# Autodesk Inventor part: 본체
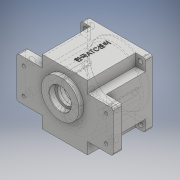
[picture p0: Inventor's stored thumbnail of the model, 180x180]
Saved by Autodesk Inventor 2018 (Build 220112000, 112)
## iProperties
Created: 2020-07
Part Number: 본체
Material: 일반
Document SubType Name: Modeling
Designer: Admin
Density: 1 g/cm^3
Appearance: 기본값
Author: Admin
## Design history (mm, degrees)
sketch "스케치5"
  geometry: L1 (47, 47)-(-47, 47); L2 (-47, 47)-(-47, -47); L3 (-47, -47)-(47, -47); L4 (47, -47)-(47, 47); L5 (47, 47)-(-47, -47); L6 (-47, 47)-(47, -47); 1 further point
  constraints: 12 end point, 2 midpoint, 2 parallel, 1 horizontal, 1 perpendicular
  dimensions: "d16" = 94 distance of L1.start L1.end; "d17" = 94 distance of L1.end L2.end
extrude "돌출5" new body sketch "스케치5" distance "d18" = 10; taper "d19" = 0 deg
sketch "스케치6"
  geometry: L1 (-33, 47)-(33, 47); L2 (33, 47)-(33, -47); L3 (33, -47)-(-33, -47); L4 (-33, -47)-(-33, 47); L5 (-33, 47)-(33, -47); L6 (33, 47)-(-33, -47); 1 further point
  constraints: 12 end point, 2 midpoint, 2 parallel, 1 horizontal, 1 perpendicular
  dimensions: "d20" = 66 distance of L1.start L1.end; "d21" = 94 distance of L1.end L2.end
extrude "돌출6" join sketch "스케치6" distance "d22" = 57; taper "d23" = 0 deg
sketch "스케치7"
  geometry: L1 (70, 30)-(70, -30); L2 (-70, -30)-(-70, 30); L3 (-70, 30)-(70, -30); L4 (70, 30)-(-70, -30); L5 (-33, 47)-(33, 47); L6 (33, -47)-(-33, -47); L7 (-33, 47)-(33, -47); L8 (33, 47)-(-33, -47); L9 (-70, 30)-(-33, 30); L10 (33, 30)-(70, 30); L11 (33, 47)-(33, 30); L12 (33, -30)-(33, -47); L13 (70, -30)-(33, -30); L14 (-33, -30)-(-70, -30); L15 (-33, -47)-(-33, -30); L16 (-33, 30)-(-33, 47); 1 further point
  constraints: 32 end point, 10 parallel, 4 midpoint, 4 perpendicular, 3 horizontal
  dimensions: "d24" = 140 distance of L2.end L1.start; "d25" = 60 distance of L1.start L1.end; "d26" = 66 distance of L5.start L5.end; "d27" = 94 distance of L5.end L6.start
extrude "돌출7" join sketch "스케치7" distance "d28" = 13; taper "d29" = 0 deg
sketch "스케치8"
  geometry: L1 (-103, 0)-(-66, 0) reference; L2 (-66, 0)-(-66, -13) reference; L3 (-103, -13)-(-66, -13) reference; L4 (-103, 0)-(-103, -13) reference; L5 (14, 67)-(-80, 67) reference; L6 (14, 67)-(14, 57) reference; L7 (0, 57)-(14, 57) reference; L8 (0, 57)-(0, -13) reference; L9 (-66, -13)-(0, -13) reference; L10 (-66, 57)-(-66, -13) reference; L11 (-80, 57)-(-66, 57) reference; L12 (-80, 67)-(-80, 57) reference; L13 (0, 0)-(37, 0) reference; L14 (37, 0)-(37, -13) reference; L15 (0, -13)-(37, -13) reference; L16 (0, 0)-(0, -13) reference; L17 (-80, 67)-(-80, 57) reference; L18 (-80, 57)-(-80, 0); L19 (-103, 0)-(-66, 0) reference; L20 (-80, 0)-(-66, 0); L21 (-66, 0)-(-66, 57); L22 (-80, 57)-(-66, 57) reference; L23 (-66, 57)-(-80, 57); L24 (14, 57)-(14, 0); L25 (0, 0)-(37, 0) reference; L26 (14, 0)-(0, 0); L27 (0, 57)-(0, -13) reference; L28 (0, 57)-(13.166, 57); L29 (0, 57)-(14, 57) reference; L30 (0, 57)-(0, 0); 1 further point
  constraints: 16 end point, 4 collinear, 4 point on line, 2 perpendicular
extrude "돌출8" join sketch "스케치8" distance "d30" = 60; taper "d31" = 0 deg
sketch "스케치9"
  geometry: L1 (-70, 30)-(-70, -30) reference; L2 (-70, -30)-(-33, -30) reference; L3 (-33, -30)-(-33, -47) reference; L4 (-33, -47)-(33, -47) reference; L5 (33, -47)-(33, -30) reference; L6 (33, -30)-(70, -30) reference; L7 (70, -30)-(70, 30) reference; L8 (70, 30)-(33, 30) reference; L9 (33, 30)-(33, 47) reference; L10 (33, 47)-(-33, 47) reference; L11 (-33, 47)-(-33, 30) reference; L12 (-33, 30)-(-70, 30) reference; L13 (-104.394, 11)-(123.857, 11); L14 (0, -65.8)-(0, 65.8) reference; C1 r 27.5 at (0, 11); 1 further point
  constraints: 2 end point, 2 point on line, 1 centre point, 1 horizontal
  dimensions: "d32" = 11 distance from line of L13 point (0, 0); "d33" = 55 diameter of C1
extrude "돌출9" join sketch "스케치9" distance "d34" = 7; taper "d35" = 0 deg
sketch "스케치10"
  geometry: C1 r 27.5 at (0, 0) reference; C2 r 16 at (0, 0); 1 further point
  constraints: 1 centre point, 1 coincident
  dimensions: "d36" = 32 diameter of C2
extrude "돌출10" cut sketch "스케치10" distance "d37" = 8.3; taper "d38" = 0 deg
sketch "스케치11"
  geometry: C1 r 16 at (0, 0) reference; C2 r 12.5 at (0, 0); 1 further point
  constraints: 1 centre point, 1 coincident
  dimensions: "d39" = 25 diameter of C2
extrude "돌출11" cut sketch "스케치11" distance "d40" = 4.7; taper "d41" = 0 deg
sketch "스케치12"
  geometry: C1 r 12.5 at (0, 0) reference; C2 r 17.5 at (0, 0); 1 further point
  constraints: 1 centre point, 1 coincident
  dimensions: "d42" = 35 diameter of C2
extrude "돌출12" cut sketch "스케치12" distance "d43" = 10; taper "d44" = 0 deg
sketch "스케치13"
  geometry: C1 r 43 at (0, 0); 1 further point
  constraints: 1 centre point, 1 coincident
  dimensions: "d45" = 86 diameter of C1
extrude "돌출13" cut sketch "스케치13" distance "d46" = 9; taper "d47" = 0 deg
sketch "스케치14"
  geometry: L1 (-98, 0)-(98, 0) reference; L2 (0, 65.8)-(0, -65.8) reference; L3 (35.778, -3.994)-(39.8, -3.994); L4 (35.778, 3.994)-(39.8, 3.994); L5 (-35.778, -3.994)-(-39.8, -3.994); L6 (-35.778, 3.994)-(-39.8, 3.994); A1 r 36 centre (0, 0) between (36, 0) and (-36, 0); A2 r 4 centre (36, 0) between (36.222, 3.994) and (36.222, -3.994); A3 r 4 centre (-36, 0) between (-36.222, -3.994) and (-36.222, 3.994); A4 r 40 centre (0, 0) between (39.8, 3.994) and (-39.8, 3.994); A5 r 40 centre (0, 0) between (-39.8, -3.994) and (39.8, -3.994); 1 further point
  constraints: 18 point on circle, 8 end point, 8 point on line, 5 centre point, 2 coincident, 1 horizontal, 1 parallel
  dimensions: "d49" = 72 diameter of A1; "d50" = 8 diameter of A3; "d51" = 8 diameter of A2; "d52" = 40 radius of A5; "d53" = 40 radius of A4
extrude "돌출14" cut sketch "스케치14" distance "d54" = 55; taper "d55" = 0 deg
sketch "스케치15"
  geometry: L1 (-78.7, -5)-(-78.7, 27) reference; L2 (-87, -5)-(-87, 27) reference; L3 (-87, 27)-(-78.7, 27) reference; L4 (-87, -5)-(-78.7, -5) reference; L5 (-86.2, 27)-(-87, 27.462); L6 (-87, 27.462)-(-87, 27); L7 (-87, 38.5)-(-87, -16.5) reference; L8 (-87, 27)-(-86.2, 27); L9 (-107.231, 11)-(-35.59, 11); 1 further point
  constraints: 8 end point, 1 collinear, 1 horizontal, 1 perpendicular, 1 point on line
  dimensions: "d56" = 30 deg angle of L3 L5; "d57" = 0.8 distance from line of L7 L5.start; "d58" = 16 distance between parallel lines of L9 L3
revolve "회전1" sketch "스케치15" stored, may be unused: angle "d59" = 90 deg
sketch "스케치16"
  geometry: L1 (83.382, 20)-(-123.857, 20); L2 (-165.305, 0)-(124.83, 0) reference; L3 (0, 65.8)-(0, -65.8) reference; C1 r 11 at (0, 20); 1 further point
  constraints: 2 end point, 2 point on line, 1 centre point, 1 horizontal
  dimensions: "d60" = 20 distance from line of point (0, 0) L1; "d61" = 22 diameter of C1
extrude "돌출15" cut sketch "스케치16" distance "d62" = 7; taper "d63" = 0 deg
sketch "스케치17"
  geometry: C1 r 11 at (0, 0) reference; C2 r 9.5 at (0, 0); 1 further point
  constraints: 1 centre point, 1 coincident
  dimensions: "d64" = 19 diameter of C2
extrude "돌출16" cut sketch "스케치17" distance "d65" = 3; taper "d66" = 0 deg
sketch "스케치18"
  geometry: C1 r 17.5 at (0, -11) reference; C2 r 11 at (0, 20) reference; C3 r 40 at (0, 0); A1 r 21 centre (0, -11) between (-8.978, 7.984) and (8.978, 7.984); A2 r 15 centre (0, 20) between (8.978, 7.984) and (-8.978, 7.984); 1 further point
  constraints: 4 point on circle, 3 centre point, 3 coincident
  dimensions: "d67" = 42 diameter of A1; "d68" = 30 diameter of A2; "d69" = 80 diameter of C3
extrude "돌출17" cut sketch "스케치18" distance "d70" = 7; taper "d71" = 0 deg
sketch "스케치19"
  geometry: A1 r 4 centre (36, 0) between (36.222, 3.994) and (36.222, -3.994) reference; A2 r 4 centre (-36, 0) between (-36.222, -3.994) and (-36.222, 3.994) reference; 3 further points
  constraints: 2 coincident
hole "구멍1" sketch "스케치19" at (36, 0), (-36, 0) diameter "d72" = 3.242; stored, may be unused: countersink angle "d76" = 90 deg, drill point angle "d78" = 118 deg; dims "d73" = 7, "d74" = 4, "d75" = 2, "d77" = 9
sketch "스케치20"
  geometry: L1 (-70, 30)-(-70, -30) reference; L2 (-70, -30)-(-33, -30) reference; L3 (-33, -30)-(-33, -47) reference; L4 (-33, -47)-(33, -47) reference; L5 (33, -47)-(33, -30) reference; L6 (33, -30)-(70, -30) reference; L7 (70, -30)-(70, 30) reference; L8 (70, 30)-(33, 30) reference; L9 (33, 30)-(33, 47) reference; L10 (33, 47)-(-33, 47) reference; L11 (-33, 47)-(-33, 30) reference; L12 (-33, 30)-(-70, 30) reference; L13 (-60, 19)-(60, 19); L14 (60, 19)-(60, -19); L15 (60, -19)-(-60, -19); L16 (-60, -19)-(-60, 19); L17 (-60, 19)-(60, -19); L18 (60, 19)-(-60, -19); C1 r 27.5 at (0, 11) reference; C2 r 2.25 at (-60, 19); C3 r 2.25 at (-60, -19); C4 r 2.25 at (60, -19); C5 r 2.25 at (60, 19); 1 further point
  constraints: 12 end point, 4 centre point, 4 coincident, 2 midpoint, 2 parallel, 1 horizontal, 1 perpendicular
  dimensions: "d79" = 38 distance of L13.end L14.end; "d80" = 120 distance of L13.start L13.end; "d81" = 4.5 diameter of C2; "d82" = 4.5 diameter of C3; "d83" = 4.5 diameter of C4; "d84" = 4.5 diameter of C5
extrude "돌출18" cut sketch "스케치20" distance "d85" = 8; taper "d86" = 0 deg
sketch "스케치21"
  geometry: L1 (-130, 11)-(-130, -49) reference; L2 (-130, -49)-(-93, -49) reference; L3 (-93, -49)-(-93, -66) reference; L4 (-93, -66)-(-27, -66) reference; L5 (-27, -66)-(-27, -49) reference; L6 (-27, -49)-(10, -49) reference; L7 (10, -49)-(10, 11) reference; L8 (10, 11)-(-27, 11) reference; L9 (-27, 11)-(-27, 28) reference; L10 (-27, 28)-(-93, 28) reference; L11 (-93, 28)-(-93, 11) reference; L12 (-93, 11)-(-130, 11) reference; C1 r 2.25 at (0, -38) reference; C2 r 2.25 at (-120, 0) reference; C3 r 2.25 at (-120, -38) reference; C4 r 2.25 at (0, 0) reference; C5 r 27.5 at (-60, -8) reference; C6 r 5 at (-120, 0); C7 r 5 at (-120, -38); C8 r 5 at (0, -38); C9 r 5 at (0, 0); 1 further point
  constraints: 4 centre point, 4 coincident
  dimensions: "d87" = 10 diameter of C9; "d88" = 10 diameter of C8; "d89" = 10 diameter of C7; "d90" = 10 diameter of C6
extrude "돌출19" cut sketch "스케치21" distance "d91" = 5; taper "d92" = 0 deg
sketch "스케치22"
  geometry: L1 (-40, 40)-(40, 40); L2 (40, 40)-(40, -40); L3 (40, -40)-(-40, -40); L4 (-40, -40)-(-40, 40); L5 (-40, 40)-(40, -40); L6 (40, 40)-(-40, -40); C1 r 3.5 at (-40, 40); C2 r 3.5 at (40, 40); C3 r 3.5 at (40, -40); C4 r 3.5 at (-40, -40); 1 further point
  constraints: 12 end point, 4 centre point, 4 coincident, 2 midpoint, 2 parallel, 1 horizontal, 1 perpendicular
  dimensions: "d93" = 80 distance of L1.start L1.end; "d94" = 80 distance of L1.end L2.end; "d95" = 7 diameter of C1; "d96" = 7 diameter of C2; "d97" = 7 diameter of C3; "d98" = 7 diameter of C4
extrude "돌출20" cut sketch "스케치22" distance "d99" = 10; taper "d100" = 0 deg
sketch "스케치23" dims "d16" = 94, "d17" = 94
  geometry: L1 (47, -104.4)-(47, 17.4) reference; L2 (0, 0)-(94, 0) reference; 2 further points
  constraints: 1 point on line, 1 other
  dimensions: "d101" = 40 distance from line of L2 point (47, -40)
feature "엠보싱1" sketch "스케치23" dims "d16" = 94, "d17" = 94, "d24" = 140, "d25" = 60, "d26" = 66, "d27" = 94, "d102" = 0.5, "d103" = 0
chamfer "모따기1" distance "d104" = 1; stored, may be unused: second distance "d105" = 2, angle "d106" = 45 deg
chamfer "모따기2" distance "d107" = 1; stored, may be unused: second distance "d108" = 2, angle "d109" = 45 deg
chamfer "모따기3" distance "d110" = 1; stored, may be unused: second distance "d111" = 2, angle "d112" = 45 deg
fillet "모깎기1" dims "d113" = 3
fillet "모깎기2" dims "d114" = 3
fillet "모깎기3" dims "d115" = 3
fillet "모깎기4" dims "d116" = 3
fillet "모깎기5" dims "d117" = 3
node "솔리드2"
node "투영된 루프4"
node "투영된 루프5"
node "투영된 루프6"
node "투영된 루프7"
node "투영된 루프8"
node "투영된 루프9"
node "투영된 루프10"
node "투영된 루프11"
node "투영된 루프12"
